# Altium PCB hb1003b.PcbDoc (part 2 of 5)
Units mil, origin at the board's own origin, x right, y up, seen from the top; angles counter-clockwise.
Board outline 2757 x 3548 mil, 2 copper layers (Top Layer, Bottom Layer); 120 components, 120 nets, 466 pads, 329 vias.
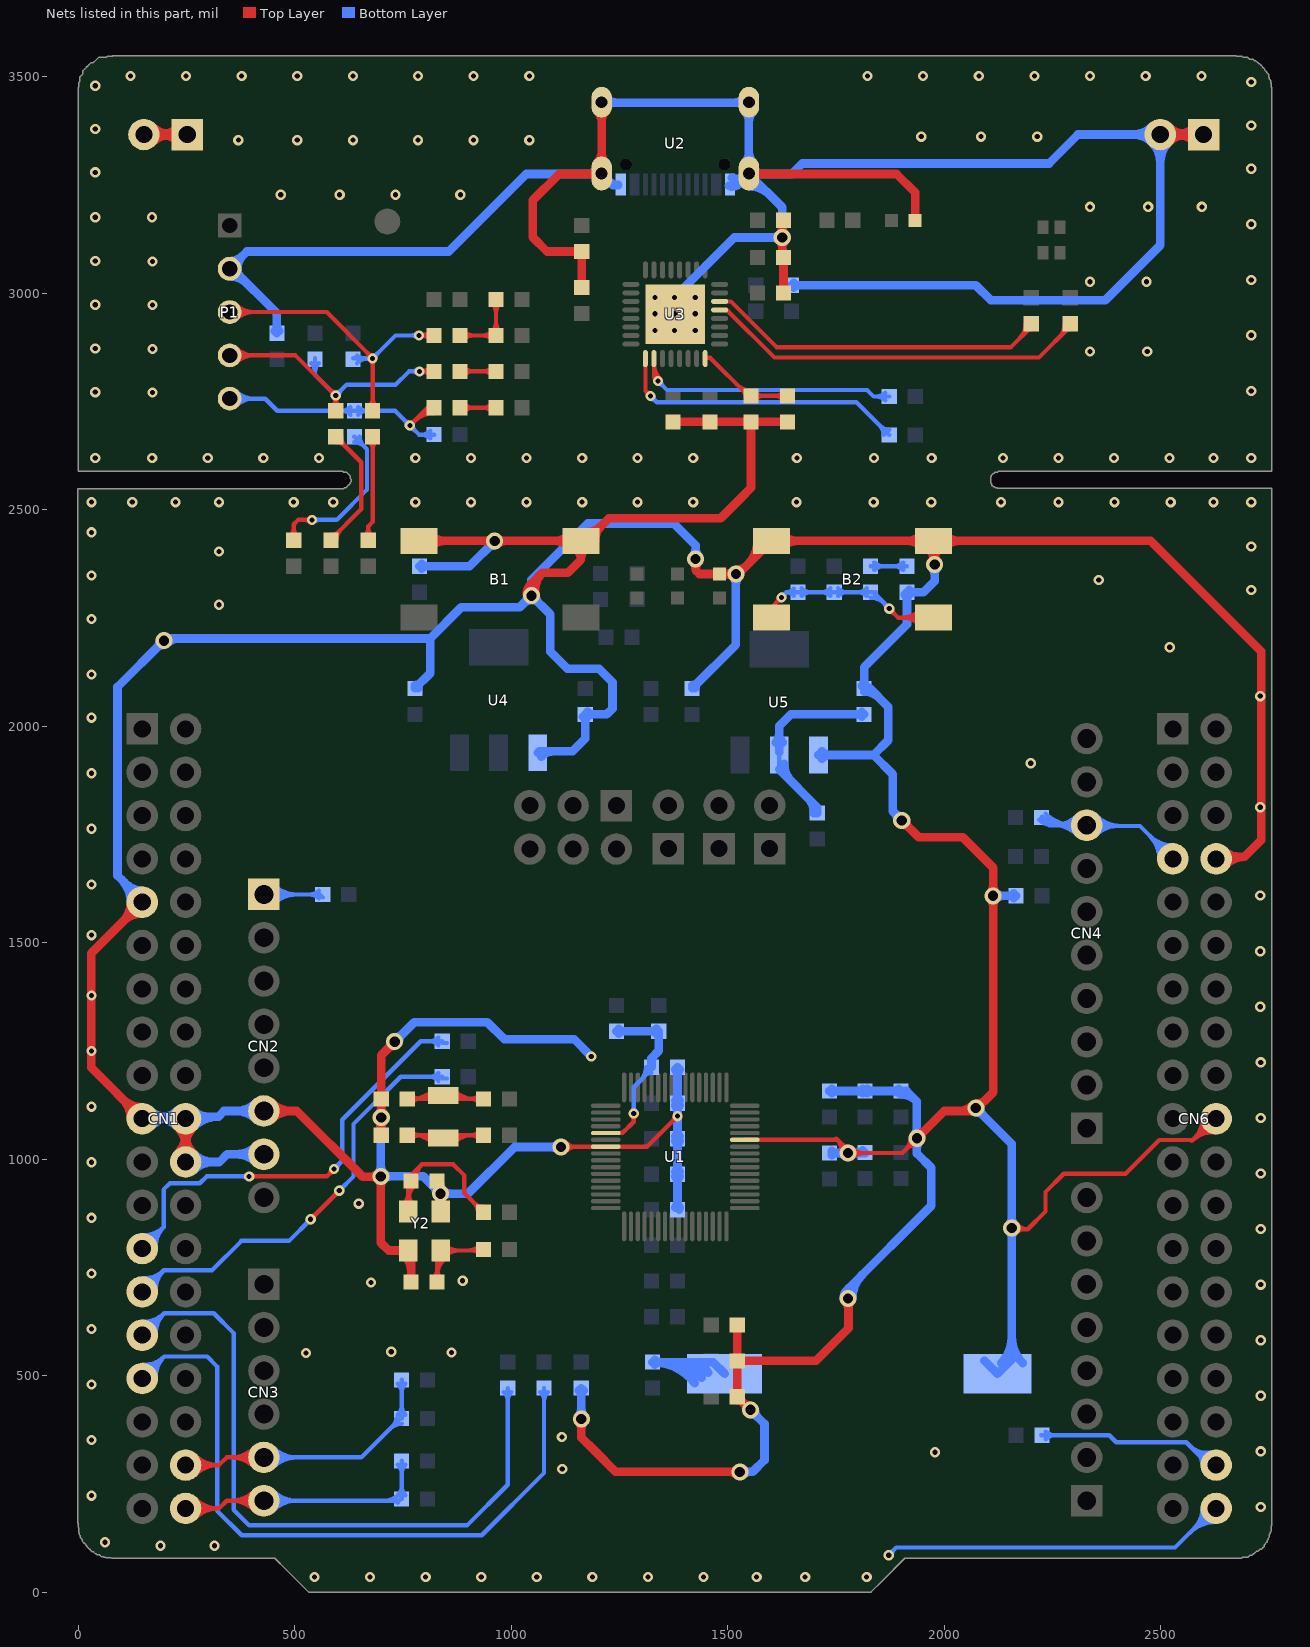
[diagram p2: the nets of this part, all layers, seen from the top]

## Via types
v1: diameter 23.62, hole 11.81, Top Layer to Bottom Layer, tented both sides, 290 vias
v2: diameter 39.37, hole 23.62, Top Layer to Bottom Layer, tented both sides, 29 vias
v3: diameter 15, hole 8, Top Layer to Bottom Layer, tented both sides, 10 vias

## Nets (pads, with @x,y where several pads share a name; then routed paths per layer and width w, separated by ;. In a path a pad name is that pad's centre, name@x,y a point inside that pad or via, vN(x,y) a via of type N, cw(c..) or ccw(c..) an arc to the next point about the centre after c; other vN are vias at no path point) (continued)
GND: B1.1 B1.2 B2.1 B2.2 BT1.2 C1.1 C2.2 C3.1 C4.2 C5.1 C6.1 C9.2 C11.2 C12.2 C13.2 C14.2 C15.2 C16.2 C17.2 C18.2 C19.2 C20.1 C21.1 C22.1 C23.1 C24.1 C25.1 C26.1 C27.1 C28.1 C29.2 C30.2 C31.1 C32.2 C34.1 C35.2 C36.1 CN1.9 CN1.19 CN1.20 CN1.22 CN2.6 CN2.7 CN6.8 CN6.20 CN6.38 D3.2 D4.2 JP2.1 JP2.2 JP3.1 JP3.2 P1.2 R5.2 R11.2 R25.2 R28.2 U1.7 U1.43 U2.1 U2.2 U2.3 U2.4 U2.A1 U2.A12 U2.B1 U2.B12 U3.33 U4.1 U5.1 Y2.2 Y2.4 | length 31589.5
  Top Layer w10: CN1.22@248,998 CN1.22@251,995 ; CN2.7@424,995 CN2.7@428,999 ; C5.1@700,1139 C5.1@709,1148 ; v2@1113.62,1028.62 U1.7@1218.57,1028.62 1313.62,1028.62 v1(1384,1099) ; v2@1125.38,1017.62 cw(c1151.95,991.05) 1151.95,1028.62 ; v2@1125.38,1038.38 ccw(c1148.95,1061.95) 1148.95,1028.62 ; B1.2@1155.58,2427.58 B1.2@1161.01,2427.58 ; v1@1377.19,1099 cw(c1360.75,1099) 1372.37,1087.37 cw(c1384,1075.75) v1@1384,1092.19 ; U1.43@1539.43,1044.37 1753.63,1044.37 v2@1778,1020 ; 1750.63,1047.37 cw(c1719.87,1016.61) v2@1763.33,1014.66 ; 1763.17,1034.83 ccw(c1778,1049.65) v2@1778,1028.68 ; 1766.68,1031.32 cw(c1750.58,1015.23) v2@1773.32,1014.21 ; v2(1778,1014) 1903,1014 v2(1937,1048) ; v2@1788.38,1003.62 cw(c1813.45,978.55) 1813.45,1014 cw(c1813.45,1049.45) v2@1788.38,1024.38 ; v2@1922.31,1048 cw(c1886.86,1048) 1911.93,1022.93 cw(c1937,997.86) v2@1937,1033.31 ; v2@2156,838 2193,838 ; v2@2166.38,830.62 cw(c2184.21,812.79) 2184.21,838 ; v2@2167.43,850.22 ccw(c2193,870.86) 2193,838 ; 2571.62,1041.62 cw(c2620.96,992.27) CN6.20@2625.81,1061.89 ; 2577.74,1047.74 ccw(c2532.26,1093.23) CN6.20@2596.58,1093.23 ; 2587.14,1057.14 cw(c2622.98,1021.29) CN6.20@2626.51,1071.86 ; 2594.81,1064.81 ccw(c2566.4,1093.23) CN6.20@2606.58,1093.23 ; CN6.20@2625.61,1095.61 2574,1044 2496.58,1044 2418.58,966 2276,966 2234,924 2234,879 2193,838
  Top Layer w20: CN1.19@121.58,1093.23 ccw(c57.81,1093.23) 102.9,1138.33 ccw(c148,1183.42) CN1.19@148,1119.65 ; CN1.9@121.58,1593.23 cw(c57.81,1593.23) 102.9,1548.13 cw(c148,1503.03) CN1.9@148,1566.81 ; CN1.19@148,1093.23 30,1211.23 30,1475.23 CN1.9@148,1593.23 ; JP3.2@152,3366 JP3.1@252,3366 ; JP3.2@170.68,3347.32 cw(c215.78,3302.22) 215.78,3366 cw(c215.78,3429.78) JP3.2@170.68,3384.68 ; CN1.22@229.32,1011.91 ccw(c184.22,1057.01) 248,1057.01 ccw(c311.78,1057.01) CN1.22@266.68,1011.91 ; CN1.20@229.32,1074.55 cw(c184.22,1029.45) 248,1029.45 cw(c311.78,1029.45) CN1.20@266.68,1074.55 ; JP3.1@233.32,3347.32 ccw(c188.22,3302.22) 188.22,3366 ccw(c188.22,3429.78) JP3.1@233.32,3384.68 ; CN1.22@248,998 CN1.20@248,1098 ; CN2.6@429,1111 505,1111 657,959 696,959 v2@700,963 ; CN2.6@447.68,1092.32 cw(c492.78,1047.22) 492.78,1111 cw(c492.78,1174.78) CN2.6@447.68,1129.68 ; 673.2,959 ccw(c673.2,985.8) v2@692.15,966.85 ; 678.03,959 cw(c678.03,939.03) 692.15,953.15 cw(c675.62,936.62) 699,936.62 cw(c722.38,936.62) v2@705.85,953.15 ; v2@693.15,1089.15 cw(c676.62,1072.62) 700,1072.62 cw(c723.38,1072.62) v2@706.85,1089.15 ; v2@693.15,1102.85 ccw(c676.62,1119.38) 700,1119.38 ccw(c723.38,1119.38) v2@706.85,1102.85 ; C6.1@694.7,1060.3 ccw(c681.89,1073.11) 700,1073.11 ccw(c718.11,1073.11) C6.1@705.3,1060.3 ; C5.1@694.7,1133.7 cw(c681.89,1120.89) 700,1120.89 cw(c718.11,1120.89) C5.1@705.3,1133.7 ; C5.1@694.7,1144.3 ccw(c681.89,1157.11) 700,1157.11 ccw(c718.11,1157.11) C5.1@705.3,1144.3 ; 699,850 699,893 ; v2(699,960) 699,893 ; C6.1@700,1055 C5.1@700,1139 700,1240 v2(731,1271) ; v2@721.32,1271 cw(c697.93,1271) 714.47,1254.47 cw(c731,1237.93) v2@731,1261.32 ; Y2.2@754.36,776.55 cw(c719.01,741.2) 769,741.2 ; Y2.2@754.36,780.48 ccw(c734.46,760.59) 734.46,788.72 ccw(c734.46,816.86) Y2.2@754.36,796.96 ; C12.2@763.7,721.3 ccw(c750.89,734.11) 769,734.11 ccw(c787.11,734.11) C12.2@774.3,721.3 ; C12.2@769,716 769,782.32 Y2.2@762.6,788.72 717.28,788.72 699,807 699,893 ; B1.1@786.99,2427.58 B1.2@1155.58,2427.58 ; B1.1@813.68,2413.5 cw(c847.68,2379.49) 847.68,2427.58 cw(c847.68,2475.68) B1.1@813.68,2441.67 ; C11.2@823.7,943.7 cw(c790.61,910.61) v2@837.4,910.61 ; C11.2@829,949 C11.2@837.4,940.6 ; Y2.4@829.16,891.45 ccw(c809.27,911.35) 837.4,911.35 ccw(c865.54,911.35) Y2.4@845.64,891.45 ; v2@830.15,913.15 cw(c812.65,895.65) Y2.4@837.4,895.65 ; v2@831.06,927.65 ccw(c821.01,940.6) C11.2@837.4,940.6 ; Y2.4@837.4,879.28 C11.2@837.4,940.6 ; Y2.4@837.4,897.59 cw(c859.41,897.59) v2@843.85,913.15 ; v2@843.41,927.26 cw(c855.21,940.6) C11.2@837.4,940.6 ; 937.21,2427.58 cw(c937.21,2402.21) v2@955.15,2420.15 ; 940.03,2427.58 ccw(c940.03,2448.97) v2@955.15,2433.85 ; v2@968.85,2420.15 cw(c986.79,2402.21) 986.79,2427.58 ; v2@968.85,2433.85 ccw(c983.97,2448.97) 983.97,2427.58 ; v2@1036.88,2298.99 cw(c1067.92,2305.16) 1045.54,2327.54 ; v2@1040.15,2307.85 ccw(c1023.62,2324.38) 1047,2324.38 ccw(c1070.38,2324.38) v2@1053.85,2307.85 ; v2(1047,2301) 1047,2329 1072,2354 ; 1050,3156 1050,3179 ; v2@1056.5,2302.89 cw(c1112.05,2313.95) 1072,2354 ; B1.2@1134.32,2413.5 ccw(c1100.32,2379.49) 1100.32,2427.58 ccw(c1100.32,2475.68) B1.2@1134.32,2441.67 ; B1.2@1147.97,2412.52 cw(c1123.32,2384.01) 1161.01,2384.01 ; v2@1155.15,393.15 cw(c1138.62,376.62) 1162,376.62 cw(c1185.38,376.62) v2@1168.85,393.15 ; C29.2@1157.7,3018.3 ccw(c1144.89,3031.11) 1163,3031.11 ccw(c1181.11,3031.11) C29.2@1168.3,3018.3 ; C31.1@1157.7,3101.3 cw(c1144.89,3114.11) 1144.89,3096 cw(c1144.89,3077.89) 1157.7,3090.7 cw(c1144.89,3077.89) 1163,3077.89 cw(c1181.11,3077.89) C31.1@1168.3,3090.7 ; v2(1162,400) 1162,357 1194,325 1241,278 v2@1528,278 ; C29.2@1163,3006 C31.1@1163,3096 1083,3096 1050,3129 1050,3179 ; B1.2@1173.61,2447.5 ccw(c1173.61,2495.54) 1207.57,2461.57 ; 1173.7,3275 ccw(c1173.7,3311.3) U2.1@1199.37,3285.63 ; B1.2@1174.04,2412.52 ccw(c1198.7,2384.01) 1161.01,2384.01 ; 1178.53,3275 cw(c1178.53,3245.53) U2.1@1199.37,3266.37 ; B1.2@1193.53,2427.58 cw(c1241.68,2427.58) 1207.63,2461.63 ; U2.1@1199.37,3301.38 ccw(c1176.49,3324.26) 1208.84,3324.26 ; U2.3@1199.37,3419.12 cw(c1176.49,3396.25) 1208.84,3396.25 ; 1208.84,3325.01 ccw(c1242.26,3325.01) U2.1@1218.63,3301.38 ; 1208.84,3395.49 cw(c1242.26,3395.49) U2.3@1218.63,3419.12 ; U2.3@1208.84,3439.57 1208.84,3275 1111,3275 1050,3214 1050,3179 ; C21.1@1369,2703 1459,2703 C28.1@1633,2703 ; C21.1@1379.3,2696.7 cw(c1394.52,2681.48) 1394.52,2703 ; v2(1426,2386) 1426,2360 1435,2351 D3.2@1481,2351 v2(1519,2351) 1524.41,2351 B2.1@1600.99,2427.58 B2.2@1975.01,2427.58 2476.42,2427.58 2732,2172 2732,1736.66 2693.34,1698 ; 1438.48,2703 cw(c1438.48,2681.48) C20.1@1453.7,2696.7 ; C20.1@1464.3,2696.7 cw(c1479.52,2681.48) 1479.52,2703 ; 1502.2,278 cw(c1502.2,251.2) v2@1521.15,270.15 ; 1507.03,278 ccw(c1507.03,297.97) v2@1521.15,283.85 ; v2@1512.15,2344.15 ccw(c1495.62,2327.62) 1495.62,2351 ccw(c1495.62,2374.38) v2@1512.15,2357.85 ; C13.2@1516.7,456.3 ccw(c1503.89,469.11) 1522,469.11 ccw(c1540.11,469.11) C13.2@1527.3,456.3 ; C14.2@1516.7,528.7 cw(c1503.89,515.89) 1522,515.89 cw(c1540.11,515.89) 1527.3,528.7 cw(c1540.11,515.89) 1540.11,534 cw(c1540.11,552.11) 1527.3,539.3 cw(c1540.11,552.11) 1522,552.11 cw(c1503.89,552.11) C14.2@1516.7,539.3 ; C15.2@1516.7,611.7 cw(c1503.89,598.89) 1522,598.89 cw(c1540.11,598.89) C15.2@1527.3,611.7 ; v2@1519,2360.69 ccw(c1519,2397.13) 1544.77,2371.36 ; C13.2@1522,443.5 cw(c1522,425.39) 1534.8,438.2 cw(c1547.61,451) C13.2@1529.5,451 ; C15.2@1522,617 C14.2@1522,534 ; 1533.48,2703 cw(c1533.48,2681.48) 1548.7,2696.7 cw(c1535.89,2683.89) 1554,2683.89 cw(c1572.11,2683.89) 1559.3,2696.7 cw(c1574.52,2681.48) 1574.52,2703 ; C13.2@1534.76,438.24 ccw(c1553,456.48) v2@1553,430.68 ; C13.2@1537.17,435.82 cw(c1522.35,421) v2@1543.32,421 ; 1540,2536 1518.5,2514.5 ; 1545.48,2372.07 ccw(c1489.96,2427.58) B2.1@1568.47,2427.58 ; U2.2@1549,3275 1890,3275 1933,3232 D4.2@1933,3168 ; v2@1550,423 C13.2@1522,451 C14.2@1522,534 ; C22.1@1554,2702 1554,2550 1518.5,2514.5 ; U2.2@1558.79,3266.37 cw(c1579.63,3245.53) 1579.63,3275 ; U2.2@1558.79,3285.63 ccw(c1584.46,3311.3) 1584.46,3275 ; 1617.48,2703 cw(c1617.48,2681.48) C28.1@1632.7,2696.7 ; v2@1619.15,3121.15 cw(c1602.62,3104.62) 1626,3104.62 cw(c1649.38,3104.62) v2@1632.85,3121.15 ; v2@1619.15,3134.85 ccw(c1602.62,3151.38) 1626,3151.38 ccw(c1649.38,3151.38) v2@1632.85,3134.85 ; C35.2@1623.7,3005.3 ccw(c1610.89,3018.11) 1629,3018.11 ccw(c1647.11,3018.11) C35.2@1634.3,3005.3 ; C32.2@1623.7,3076.7 cw(c1610.89,3063.89) 1629,3063.89 cw(c1647.11,3063.89) C32.2@1634.3,3076.7 ; C32.2@1626,3085 C34.1@1626,3168 ; 1626,3107.35 ccw(c1654.35,3107.35) C32.2@1634.3,3087.3 ; v2@1626,3142.65 cw(c1654.35,3142.65) C34.1@1634.3,3162.7 ; B2.1@1627.68,2413.5 cw(c1661.68,2379.49) 1661.68,2427.58 cw(c1661.68,2475.68) B2.1@1627.68,2441.67 ; C35.2@1629,3000 C32.2@1629,3082 ; v2@1771.15,671.15 cw(c1752.2,652.2) 1779,652.2 ; 1779,657.03 cw(c1798.97,657.03) v2@1784.85,671.15 ; v2@1779,678 1779,609 1704,534 C14.2@1522,534 ; v2@1902,1772.32 cw(c1902,1748.93) 1918.53,1765.47 cw(c1935.07,1782) v2@1911.68,1782 ; v2(1902,1782) 1941,1743 2043,1743 2113,1673 v2(2113,1608) ; v2(1937,1048) 2000,1111 2070,1111 2113,1154 v2(2113,1608) ; v2@1937,1057.68 ccw(c1937,1081.07) 1953.53,1064.53 ccw(c1970.07,1048) v2@1946.68,1048 ; B2.2@1948.32,2413.5 ccw(c1914.32,2379.49) 1914.32,2427.58 ccw(c1914.32,2475.68) B2.2@1948.32,2441.67 ; B2.2@1961.04,2413.38 cw(c1921.26,2372.92) v2@1978,2372.92 ; v2@1971.15,2379.85 ccw(c1954.62,2396.38) 1978,2396.38 ccw(c2001.38,2396.38) v2@1984.85,2379.85 ; v2(1978,2373) B2.2@1978,2424.59 ; v2@1978,2386.71 cw(c2015.88,2386.71) B2.2@1989.09,2413.5 ; B2.2@2001.69,2413.5 cw(c2035.7,2379.49) 2035.7,2427.58 cw(c2035.7,2475.68) B2.2@2001.69,2441.67 ; 2032.72,1111 ccw(c2032.72,1158.28) v2@2066.15,1124.85 ; v2@2073,1127.68 ccw(c2073,1160.72) 2096.36,1137.36 ; v2@2106.15,1601.15 cw(c2089.62,1584.62) 2113,1584.62 cw(c2136.38,1584.62) v2@2119.85,1601.15 ; v2@2106.15,1614.85 ccw(c2089.62,1631.38) 2113,1631.38 ccw(c2136.38,1631.38) v2@2119.85,1614.85 ; v2@2115,1606 v2(2113,1608) ; JP2.2@2499,3366 JP2.1@2599,3366 ; JP2.2@2517.68,3347.32 cw(c2562.78,3302.22) 2562.78,3366 cw(c2562.78,3429.78) JP2.2@2517.68,3384.68 ; JP2.1@2580.32,3347.32 ccw(c2535.22,3302.22) 2535.22,3366 ccw(c2535.22,3429.78) JP2.1@2580.32,3384.68 ; CN6.8@2628,1698 2693.34,1698 ; CN6.8@2646.68,1711.91 ccw(c2680.26,1745.48) 2680.26,1698 ; CN6.8@2648.54,1676.62 cw(c2693.33,1640.4) 2693.33,1698 ; 1072,2354 1131,2354 1161.01,2384.01 ; 1161.01,2384.01 B1.2@1161.01,2427.58 1173.58,2427.58 1226,2480 1484,2480 1518.5,2514.5 ; 1426,2362.62 cw(c1449.38,2362.62) 1432.85,2379.15 ccw(c1449.38,2362.62) 1426,2362.62 ; 1426,2362.62 ccw(c1402.62,2362.62) 1419.15,2379.15 cw(c1402.62,2362.62) 1426,2362.62
  Bottom Layer w10: v1(1185,1237) v1@1185.5,1236.5 ; v1@1872,86 1880,94 1889,103 2533,103 CN6.38@2628,198 ; v1@1872,91.81 ccw(c1872,105.84) 1881.92,95.92 ; v1@1878.81,85 cw(c1897.67,85) 1884.33,98.33 ; 2566.22,136.22 cw(c2628,74.44) CN6.38@2628,161.81 ; 2577.74,147.74 ccw(c2532.26,193.23) CN6.38@2596.58,193.23 ; 2583.29,153.29 cw(c2628,108.58) CN6.38@2628,171.81 ; 2594.81,164.81 ccw(c2566.4,193.23) CN6.38@2606.58,193.23
  Bottom Layer w20: 99.53,1646.47 cw(c46.29,1593.23) CN1.9@121.58,1593.23 ; 111.05,1634.95 ccw(c148,1671.9) CN1.9@148,1619.65 ; CN1.19@148,1098 248,1098 324,1098 337,1111 CN2.6@429,1111 ; CN1.9@148,1598 91,1655 91,2090 v2(198,2197) 203,2202 813,2202 ; CN1.19@166.68,1074.55 cw(c223.3,1017.93) CN1.20@223.3,1098 ; CN1.19@166.68,1111.91 ccw(c200.26,1145.48) 200.26,1098 ; CN1.19@172.7,1098 cw(c172.7,1017.93) CN1.20@229.32,1074.55 ; v2@188.32,2197 cw(c164.93,2197) 181.47,2180.47 cw(c198,2163.93) v2@198,2187.31 ; 195.74,1098 ccw(c195.74,1145.48) CN1.20@229.32,1111.91 ; v2@204.85,2190.15 cw(c233.45,2161.55) 233.45,2202 ; CN1.22@248,993.23 326.23,993.23 344,1011 CN2.7@429,1011 ; CN1.22@266.68,974.55 cw(c311.78,929.45) 311.78,993.23 cw(c311.78,1057.01) CN1.22@266.68,1011.91 ; CN1.20@266.68,1074.55 cw(c323.3,1017.93) 323.3,1098 ; CN1.20@266.68,1111.91 ccw(c300.26,1145.48) 300.26,1098 ; P1.2@350,3038.5 cw(c350,2981.77) 390.12,3021.88 ; P1.2@350,3073.5 ccw(c350,3115.75) 379.87,3085.87 ccw(c409.75,3056) 367.5,3056 ccw(c395.26,3056) 375.63,3036.37 ; CN2.7@410.32,992.32 ccw(c365.22,947.22) 365.22,1011 ccw(c365.22,1074.78) CN2.7@410.32,1029.68 ; CN2.6@410.32,1092.32 ccw(c365.22,1047.22) 365.22,1111 ccw(c365.22,1174.78) CN2.6@410.32,1129.68 ; R28.2@453.7,2912.3 ccw(c440.89,2925.11) 459,2925.11 ccw(c477.11,2925.11) R28.2@464.3,2912.3 ; R28.2@459,2907 459,2953 356,3056 P1.2@350,3056 390,3096 546,3096 ; 572,3096 546,3096 ; 680,3096 632,3096 ; v2@692.15,966.85 ccw(c675.62,983.38) 699,983.38 ccw(c722.38,983.38) 705.85,966.85 ccw(c722.38,983.38) 722.38,960 ccw(c722.38,936.62) v2@705.85,953.15 ; v2@693.15,1089.15 cw(c679.03,1075.03) 699,1075.03 ; 699,1070.2 cw(c725.8,1070.2) v2@706.85,1089.15 ; v2@699,1089 v2(699,960) 797,960 v2(837,920) 900,920 1008,1028 v2(1115,1028) ; v2(731,1271) 776,1316 945,1316 984,1277 1145,1277 v1(1185,1237) ; v2@731,1280.68 ccw(c731,1304.07) 747.53,1287.53 ccw(c764.07,1271) v2@740.68,1271 ; C23.1@778,2087 813,2122 813,2202 ; C23.1@778,2094.5 ccw(c778,2112.61) 790.8,2099.8 ccw(c803.61,2087) C23.1@785.5,2087 ; C2.2@788,2369 904,2369 v2(962,2427) ; C2.2@793.3,2363.7 cw(c806.11,2350.89) 806.11,2369 cw(c806.11,2387.11) C2.2@793.3,2374.3 ; v2@827.32,920 ccw(c803.93,920) 820.47,936.53 ccw(c837,953.07) v2@837,929.68 ; v2@843.85,913.15 cw(c860.38,896.62) 860.38,920 cw(c860.38,943.38) v2@843.85,926.85 ; v2@952.32,2427 cw(c928.93,2427) 945.47,2410.47 cw(c962,2393.93) v2@962,2417.31 ; v2@1037.32,2301 cw(c1013.93,2301) 1030.47,2284.47 cw(c1047,2267.93) 1047,2291.31 cw(c1047,2267.93) 1063.53,2284.47 cw(c1080.07,2301) v2@1056.68,2301 ; v2@1040.15,2307.85 ccw(c1023.62,2324.38) 1047,2324.38 ccw(c1070.38,2324.38) v2@1053.85,2307.85 ; U4.1@1061.55,1937.95 1065.1,1941.5 1141.5,1941.5 1171,1971 C25.1@1171,2027 1221,2027 1234,2040 1234,2101 1203,2132 1130,2132 1090,2172 1090,2258 v2(1047,2301) ; U4.1@1069.79,1929.71 cw(c1098.25,1901.26) 1098.25,1941.5 ; v2@1108.15,1021.15 ccw(c1091.62,1004.62) 1091.62,1028 ccw(c1091.62,1051.38) v2@1108.15,1034.85 ; v2@1155.15,406.85 ccw(c1138.62,423.38) 1162,423.38 ccw(c1185.38,423.38) v2@1168.85,406.85 ; R11.2@1156.7,465.7 cw(c1143.89,452.89) 1162,452.89 cw(c1180.11,452.89) R11.2@1167.3,465.7 ; v2(1162,400) R11.2@1162,471 ; C25.1@1165.7,2021.7 cw(c1152.89,2008.89) 1171,2008.89 cw(c1189.11,2008.89) 1176.3,2021.7 cw(c1189.11,2008.89) 1189.11,2027 cw(c1189.11,2045.11) C25.1@1176.3,2032.3 ; 1173.7,3275 ccw(c1173.7,3311.3) U2.1@1199.37,3285.63 ; 1178.53,3275 cw(c1178.53,3245.53) U2.1@1199.37,3266.37 ; U2.3@1208.84,3439.57 1549,3439.57 U2.2@1549,3275 ; U2.3@1218.63,3430.93 cw(c1239.47,3410.09) 1239.47,3439.57 ; U2.3@1218.63,3450.2 ccw(c1244.3,3475.87) 1244.3,3439.57 ; U2.1@1221.4,3265.9 ccw(c1247.03,3277.57) 1247.03,3249.4 1234.44,3249.4 1208.84,3275 1035,3275 856,3096 632,3096 ; v1(1377,2990) 1515,3128 v2(1626,3128) ; C1.1@1378.7,888.3 ccw(c1365.89,901.11) 1384,901.11 ccw(c1402.1,901.1) C1.1@1389.3,888.3 ; C3.1@1378.7,959.7 cw(c1365.89,946.89) 1384,946.89 cw(c1402.1,946.89) C3.1@1389.3,959.7 ; C3.1@1378.7,970.3 ccw(c1365.89,983.11) 1384,983.11 ccw(c1402.11,983.11) C3.1@1389.3,970.3 ; C9.2@1378.7,1041.7 cw(c1365.89,1028.89) 1384,1028.89 cw(c1402.11,1028.89) C9.2@1389.3,1041.7 ; C9.2@1378.7,1052.3 ccw(c1365.89,1065.11) 1384,1065.11 ccw(c1402.11,1065.11) C9.2@1389.3,1052.3 ; C4.2@1378.7,1123.7 cw(c1365.89,1110.89) 1384,1110.89 cw(c1402.11,1110.89) C4.2@1389.3,1123.7 ; C4.2@1378.7,1134.3 ccw(c1365.89,1147.11) 1384,1147.11 ccw(c1402.11,1147.11) C4.2@1389.3,1134.3 ; C24.1@1378.7,1206.7 cw(c1365.89,1193.89) 1384,1193.89 cw(c1402.11,1193.89) C24.1@1389.3,1206.7 ; C3.1@1384,964 1384,887.5 C1.1@1388.5,883 ; C3.1@1384,965 C9.2@1384,1047 C4.2@1384,1129 C24.1@1384,1212 ; C26.1@1418,2087 1519,2188 v2(1519,2351) ; C26.1@1418,2094.5 ccw(c1418,2112.61) 1430.8,2099.8 ccw(c1443.61,2087) C26.1@1425.5,2087 ; v2@1419.15,2392.85 ccw(c1402.62,2409.38) 1426,2409.38 ccw(c1449.38,2409.38) v2@1432.85,2392.85 ; v2(1426,2386) 1426,2417 1375.31,2467.69 1176.69,2467.69 1047,2338 v2(1047,2301) ; U2.B1@1502.75,3247.44 ccw(c1510.57,3268.98) 1526.78,3252.78 ; U2.A12@1509.57,3266.24 ccw(c1522.4,3301.6) U2.2@1549,3275 ; v2@1512.15,2344.15 cw(c1495.62,2327.62) 1519,2327.62 cw(c1542.38,2327.62) v2@1525.85,2344.15 ; 1513.86,3439.57 ccw(c1513.86,3475.87) U2.4@1539.52,3450.2 ; 1518.68,3439.57 cw(c1518.68,3410.09) U2.4@1539.52,3430.93 ; v2@1529,278 1558,278 1585,305 1585,388 v2@1552.5,420.5 ; v2@1534.85,270.15 cw(c1553.8,251.2) 1553.8,278 ; v2@1534.85,283.85 ccw(c1548.97,297.97) 1548.97,278 ; U2.2@1536.8,3265.99 cw(c1510.81,3278.05) 1510.81,3249.4 1523.4,3249.4 U2.2@1549,3275 ; U2.2@1539.52,3301.38 ccw(c1516.65,3324.26) 1549,3324.26 ; U2.4@1539.52,3419.12 cw(c1516.65,3396.25) 1549,3396.25 ; 1549,3325.01 ccw(c1582.42,3325.01) U2.2@1558.79,3301.38 ; 1549,3395.49 cw(c1582.42,3395.49) U2.4@1558.79,3419.12 ; U2.2@1549.16,3246.63 cw(c1549.16,3178.52) 1597.32,3226.68 ; U2.2@1549.16,3275 1648,3275 1672,3299 2242,3299 2309,3366 JP2.2@2499,3366 2499,3110 2372,2983 2108,2983 2073,3018 C30.2@1647,3018 ; v2@1553,411.32 cw(c1553,390.35) 1567.83,405.17 ; U2.2@1558.79,3266.37 cw(c1579.63,3245.53) 1579.63,3275 ; U2.2@1558.79,3285.63 ccw(c1584.46,3311.3) 1584.46,3275 ; v2@1562.68,421 ccw(c1588.48,421) 1570.24,402.76 ; v2@1619.15,3121.15 ccw(c1602.62,3104.62) 1602.62,3128 ccw(c1602.62,3151.38) v2@1619.15,3134.85 ; C30.2@1652.3,3012.7 cw(c1665.11,2999.89) 1665.11,3018 cw(c1665.11,3036.11) C30.2@1652.3,3023.3 ; U5.1@1709.55,1932.95 1836.95,1932.95 ; U5.1@1717.79,1924.71 cw(c1737.69,1904.82) 1737.69,1932.95 cw(c1737.69,1961.09) U5.1@1717.79,1941.19 ; C17.2@1735,1157 C19.2@1817,1157 C36.1@1900,1157 1913,1157 1937,1133 v2(1937,1048) 1937,1013 1970,980 1970,892 1779,701 ; C18.2@1740.3,1008.7 cw(c1753.11,995.89) 1753.11,1014 cw(c1753.1,1032.1) C18.2@1740.3,1019.3 ; C17.2@1740.3,1151.7 cw(c1753.11,1138.89) 1753.11,1157 cw(c1753.11,1175.11) C17.2@1740.3,1162.3 ; C18.2@1741,1014 v2(1778,1014) C16.2@1817,1014 ; v2@1767.69,678 cw(c1795.9,678) 1775.95,697.95 ; v2@1771.15,1007.15 ccw(c1754.62,990.62) 1754.62,1014 ccw(c1754.62,1037.38) v2@1771.15,1020.85 ; v2@1771.75,685.4 ccw(c1758.59,701) 1779,701 ; v2@1779,686 1779,701 ; 1779,698.97 ccw(c1798.97,698.97) v2@1784.85,684.85 ; v2@1784.85,1007.15 cw(c1801.38,990.62) 1801.38,1014 cw(c1801.38,1037.38) v2@1784.85,1020.85 ; v2@1787.68,678 cw(c1864.18,678) 1810.09,732.09 ; v2@1796.48,1014 ccw(c1796.48,1035.52) C16.2@1811.7,1020.3 ; C27.1@1809.7,2092.3 ccw(c1796.89,2105.11) 1815,2105.11 ccw(c1833.11,2105.11) C27.1@1820.3,2092.3 ; C19.2@1811.7,1151.7 ccw(c1798.89,1138.89) 1798.89,1157 ccw(c1798.89,1175.11) C19.2@1811.7,1162.3 ; C27.1@1815,2079.5 cw(c1815,2030.01) 1850,2065.01 ; C27.1@1815,2087 1815,2136 1914,2235 R5.2@1914,2309 1952,2309 1978,2335 v2(1978,2373) ; C19.2@1822.3,1151.7 cw(c1835.11,1138.89) 1835.11,1157 cw(c1835.11,1175.11) C19.2@1822.3,1162.3 ; C27.1@1828,2087 1871,2044 1871,1967 1836.95,1932.95 ; v2@1892.32,1782 ccw(c1868.93,1782) 1885.47,1798.53 ccw(c1902,1815.07) v2@1902,1791.68 ; C36.1@1894.7,1151.7 ccw(c1881.89,1138.89) 1881.89,1157 ccw(c1881.89,1175.11) C36.1@1894.7,1162.3 ; C36.1@1900,1149.5 cw(c1900,1100.01) 1935,1135 ; v2(1902,1782) 1880.95,1803.05 1880.95,1888.95 1836.95,1932.95 ; R5.2@1908.7,2303.7 cw(c1895.89,2290.89) 1914,2290.89 cw(c1932.11,2290.89) 1919.3,2303.7 cw(c1932.11,2290.89) 1932.11,2309 cw(c1932.11,2327.11) R5.2@1919.3,2314.3 ; v2@1930.15,1041.15 cw(c1913.62,1024.62) 1937,1024.62 cw(c1960.38,1024.62) v2@1943.85,1041.15 ; v2@1930.15,1054.85 ccw(c1913.62,1071.38) 1937,1071.38 ccw(c1960.38,1071.38) v2@1943.85,1054.85 ; v2@1971.15,2366.15 cw(c1954.62,2349.62) 1978,2349.62 cw(c2001.38,2349.62) v2@1984.85,2366.15 ; v2@2073,1108.32 cw(c2073,1084.93) 2089.53,1101.47 cw(c2106.07,1118) v2@2082.68,1118 ; v2(2073,1118) 2156,1035 v2@2156,851 ; BT1.2@2093,533.92 BT1.2@2122.92,504 2156,537.08 v2(2156,841) ; v2(2113,1608) R25.2@2166,1608 R25.2@2164,1606 ; v2@2119.85,1601.15 cw(c2136.38,1584.62) 2136.38,1608 cw(c2136.38,1631.38) v2@2119.85,1614.85 ; BT1.2@2131.44,528.94 ccw(c2072.15,588.23) 2156,588.23 ; v2@2149.15,834.15 cw(c2132.62,817.62) 2156,817.62 cw(c2179.38,817.62) v2@2162.85,834.15 ; v2@2149.15,847.85 ccw(c2132.62,864.38) 2156,864.38 ccw(c2179.38,864.38) v2@2162.85,847.85 ; 2156,590.09 ccw(c2242.48,590.09) BT1.2@2181.33,528.94 ; R25.2@2160.7,1602.7 ccw(c2147.89,1589.89) 2147.89,1608 ccw(c2147.89,1626.11) R25.2@2160.7,1613.3 ; JP2.2@2480.32,3384.68 cw(c2435.22,3429.78) 2435.22,3366 cw(c2435.22,3302.22) 2480.32,3347.32 cw(c2435.22,3302.22) 2499,3302.22 cw(c2562.78,3302.22) JP2.2@2517.68,3347.32 ; 546,3096 632,3096 ; 813,2202 885,2274 1020,2274 v2(1047,2301) ; U2.2@1549,3275 1626,3198 ; v2@1619.15,3134.85 ccw(c1602.62,3151.38) 1626,3151.38 ; v2@1619.15,3134.85 ccw(c1602.62,3151.38) 1626,3151.38 ; v2(1626,3128) 1626,3198 ; v2(1626,3128) 1626,3198 ; 1626,3151.38 ccw(c1649.38,3151.38) 1632.85,3134.85 cw(c1649.38,3151.38) 1626,3151.38
  other v1: 545.82,34.66 674.16,34.66 802.49,34.66 930.83,34.66 1059.17,34.66 1187.5,34.66 1315.84,34.66 1444.17,34.66 1567,34.66 1679,34.66 1821,34.66 1872,85 190.34,107 314.67,107 62,115 2731,196.64 31,222.64 1118,284 1979,323 2731,324.97 31,350.97 1117,358 2731,453.31 31,479.31 526,552 862,553 723,555 2731,581.64 31,607.64 2731,709.98 676,715 888,719 31,735.98 2731,838.32 31,864.32 648,897 2731,966.65 31,992.65 2731,1094.99 31,1120.99 2731,1223.32 31,1249.32 2730,1351.66 31,1377.66 2730,1479.99 31,1516.99 2730,1608.33 31,1634.33 31,1762.66 2730,1812.32 31,1891 2200,1914 31,2019.34 2730,2068.99 31,2119 2521,2182 31,2247.34 325,2280 2709,2314.34 2357,2337 31,2347.34 325,2403 2709,2414.34 31,2447.34 31,2517 125,2517 225,2517 325,2517 497.65,2517 589,2517 778.67,2517 907.01,2517 1035.67,2517 1164.01,2517 1292.01,2517 1420.34,2517 1658.77,2517 1837.18,2517 1970.04,2517 2131,2517 2263.91,2517 2393.49,2517 2523,2517 2622,2517 2709,2517 39.57,2619 170.99,2619 299.33,2619 427.66,2619 556,2619 778.67,2619 907.01,2619 1035.67,2619 1164.01,2619 1292.01,2619 1420.34,2619 1659.77,2619 1838.18,2619 1971.04,2619 2135.57,2619 2263.91,2619 2392.25,2619 2520.58,2619 2622,2619 2709,2619 171.57,2770 39.57,2771 2709,2773.99 2337,2865 2468.99,2865 171.57,2871 39.57,2872 2709,2902.33 1332,2913 1377,2913 1425,2913 1332,2952 1377,2952 1425,2952 171.57,2972 39.57,2973 1332,2990 1425,2990 2337,3026 2466.99,3026 2709,3030.33 171.57,3073 39.57,3074 2709,3158.66 39.57,3175 170.57,3175 2337,3199 2471,3199 2595,3199 468,3227 603.99,3227 733,3227 882.66,3227 39.57,3278.68 2709,3287 370,3353 505.99,3353 635,3353 784.66,3353 912.99,3353 1042,3353 1947,3361 2085,3361 2215,3361 39.57,3378.68 2709,3387 39.57,3478.68 2709,3487 120.66,3501 248.99,3501 377.66,3501 505.99,3501 635,3501 784.66,3501 912.99,3501 1042,3501 1822.99,3501 1951.33,3501 2079.99,3501 2208.33,3501 2337,3501 2465.33,3501 2594,3501
  other v2: 1528,277 1553,421 1778,678 700,1096
HED_LINK_LEDG: R33.1 U3.5 | length 940.2
  Top Layer w10: U3.5@1479.39,2960.84 1498.09,2960.84 1607.94,2851 1837,2851 2219,2851 R33.1@2291,2923 ; U3.5@1495.54,2960.33 cw(c1495.54,2952.92) 1500.78,2958.16 ; 2265.42,2897.42 ccw(c2233.84,2929) R33.1@2278.5,2929 ; R33.1@2279.9,2911.9 cw(c2291,2900.81) R33.1@2291,2916.5
HED_LINK_LEDR: R32.1 U3.6 | length 851.6
  Top Layer w10: U3.6@1479.39,2980.53 1507.38,2980.53 1612.91,2875 2154,2875 R32.1@2202,2923 ; 2174.71,2895.71 ccw(c2141.42,2929) R32.1@2188.5,2929 ; R32.1@2191.61,2912.61 cw(c2201,2903.22) R32.1@2201,2916.5 ; R32.1@2191.78,2912.78 ccw(c2175.57,2929) R32.1@2198.5,2929
HED_LINK_RESET: R38.1 R50.2 | length 177.8
  Top Layer w10: R38.1@882,2735 R50.2@965,2735 ; R38.1@890.84,2726.16 cw(c912.18,2704.82) 912.18,2735 cw(c912.18,2765.18) R38.1@890.84,2743.84 ; R50.2@956.16,2726.16 ccw(c934.82,2704.82) 934.82,2735 ccw(c934.82,2765.18) R50.2@956.16,2743.84
HED_LINK_SWCLK: R41.1 R51.2 | length 177.8
  Top Layer w10: R41.1@882,2819 R51.2@965,2819 ; R41.1@890.84,2810.16 cw(c912.18,2788.82) 912.18,2819 cw(c912.18,2849.18) R41.1@890.84,2827.84 ; R51.2@956.16,2810.16 ccw(c934.82,2788.82) 934.82,2819 ccw(c934.82,2849.18) R51.2@956.16,2827.84
HED_LINK_SWDIO: R37.1 R42.2 R43.2 | length 355.6
  Top Layer w10: R37.1@882,2902 R42.2@965,2902 R43.2@965,2985 ; R37.1@890.84,2893.16 cw(c912.18,2871.82) 912.18,2902 cw(c912.18,2932.18) R37.1@890.84,2910.84 ; R42.2@956.16,2893.16 ccw(c934.82,2871.82) 934.82,2902 ccw(c934.82,2932.18) 956.16,2910.84 ccw(c934.82,2932.18) 965,2932.18 ccw(c995.18,2932.18) R42.2@973.84,2910.84 ; R43.2@956.16,2976.16 cw(c934.82,2954.82) 965,2954.82 cw(c995.18,2954.82) R43.2@973.84,2976.16
HED_LINK_USART_RX: R39.1 U3.26 | length 735.8
  Top Layer w10: 1329.79,2811.54 ccw(c1353.54,2811.54) v1@1336.75,2794.75 ; U3.26@1329.79,2835.68 ccw(c1377.68,2835.68) v1@1343.82,2801.82 ; U3.26@1329.79,2850.61 1329.79,2806.21 v1(1339,2797)
  Bottom Layer w10: v1@1339,2790.19 cw(c1339,2773.75) 1350.63,2785.37 cw(c1362.25,2797) v1@1345.81,2797 ; v1(1339,2797) 1360,2776 1822,2776 1837,2761 R39.1@1873,2761 ; R39.1@1864.16,2752.16 ccw(c1842.82,2730.82) 1842.82,2761 ccw(c1842.82,2791.18) R39.1@1864.16,2769.84
HED_LINK_USART_TX: R40.1 U3.25 | length 779.5
  Top Layer w10: U3.25@1310.1,2850.61 1310.1,2773.9 v1@1321,2763 ; v1@1315.19,2762 ccw(c1298.75,2762) 1310.37,2773.63 ccw(c1322,2785.25) v1@1322,2768.81
  Bottom Layer w10: v1@1322,2755.19 cw(c1322,2738.75) 1333.63,2750.37 cw(c1345.25,2762) v1@1328.81,2762 ; v1(1322,2762) 1336,2748 1797,2748 R40.1@1873,2672 ; R40.1@1860.5,2672 ccw(c1830.32,2672) 1851.66,2693.34 ccw(c1873,2714.68) R40.1@1873,2684.5
LINK_MCU_NRST: P1.5 R38.2 R46.2 R49.2 | length 1017.1
  Top Layer w10: v1(766,2694) 807,2735 R38.2@822,2735 ; v1@766,2700.81 ccw(c766,2717.25) 777.63,2705.63 ccw(c789.25,2694) v1@772.81,2694 ; 775.06,2703.06 cw(c822,2656.11) R38.2@822,2722.5 ; 792.13,2720.13 cw(c822,2690.25) R38.2@822,2732.5
  Bottom Layer w10: P1.5@350,2756 432,2756 460,2728 R49.2@638,2728 732,2728 v1(766,2694) 787,2673 R46.2@822,2673 ; P1.5@358.84,2747.16 cw(c380.18,2725.82) 380.18,2756 cw(c380.18,2786.18) P1.5@358.84,2764.84 ; P1.5@365.91,2740.09 cw(c404.32,2701.68) 404.32,2756 cw(c404.32,2810.32) P1.5@365.91,2771.91 ; R49.2@629.16,2719.16 ccw(c607.82,2697.82) 607.82,2728 ccw(c607.82,2758.18) R49.2@629.16,2736.84 ; R49.2@646.84,2719.16 cw(c668.18,2697.82) 668.18,2728 cw(c668.18,2758.18) R49.2@646.84,2736.84 ; v1@759.19,2694 ccw(c742.75,2694) 754.37,2705.63 ccw(c766,2717.25) v1@766,2700.81 ; v1@766,2687.19 cw(c766,2670.75) 777.63,2682.37 cw(c789.25,2694) v1@772.81,2694 ; R46.2@813.16,2664.16 ccw(c791.82,2642.82) 791.82,2673 ccw(c791.82,2703.18) R46.2@813.16,2681.84
LINK_MCU_SWCLK: P1.4 R41.2 R44.2 R47.2 | length 1104.5
  Top Layer w10: P1.4@350,2856 502,2856 v1(595,2763) R47.2@595,2728 ; P1.4@358.84,2847.16 cw(c380.18,2825.82) 380.18,2856 cw(c380.18,2886.18) P1.4@358.84,2864.84 ; P1.4@365.91,2840.09 cw(c404.32,2801.68) 404.32,2856 cw(c404.32,2910.32) P1.4@365.91,2871.91 ; R47.2@586.16,2736.84 ccw(c564.83,2758.17) v1@595,2758.17 ; v1@588.19,2763 ccw(c571.75,2763) 583.37,2774.63 ccw(c595,2786.25) v1@595,2769.81 ; v1@590.18,2758.18 cw(c578.56,2746.56) 595,2746.56 cw(c611.45,2746.55) v1@599.82,2758.18 ; v1@595,2758.18 ccw(c625.18,2758.18) R47.2@603.84,2736.84 ; v1(788,2819) R41.2@822,2819 ; v1@792.82,2814.18 cw(c804.45,2802.55) 804.45,2819 cw(c804.44,2835.44) v1@792.82,2823.82 ; R41.2@813.16,2810.16 ccw(c791.82,2788.82) 791.82,2819 ccw(c791.82,2849.18) R41.2@813.16,2827.84
  Bottom Layer w10: R44.2@538.16,2838.16 cw(c516.82,2816.82) 547,2816.82 cw(c577.18,2816.82) R44.2@555.84,2838.16 ; R44.2@547,2849 R44.2@547,2847 547,2811 v1(595,2763) 620,2788 733,2788 764,2819 v1(788,2819) ; v1@588.19,2763 ccw(c571.75,2763) 583.37,2774.63 ccw(c595,2786.25) 595,2769.81 ccw(c595,2786.25) 606.63,2774.63 ccw(c618.25,2763) v1@601.81,2763 ; v1@783.18,2814.18 ccw(c771.56,2802.56) 771.56,2819 ccw(c771.56,2835.44) v1@783.18,2823.82
LINK_MCU_SWDIO: P1.3 R37.2 R45.2 R48.2 | length 1134.8
  Top Layer w10: P1.3@350,2956 574,2956 680,2850 R48.2@680,2728 ; P1.3@358.84,2947.16 cw(c380.18,2925.82) 380.18,2956 cw(c380.18,2986.18) P1.3@358.84,2964.84 ; P1.3@365.91,2940.09 cw(c404.32,2901.68) 404.32,2956 cw(c404.32,3010.32) P1.3@365.91,2971.91 ; 667.67,2862.33 cw(c654.33,2849) v1@673.19,2849 ; 670.08,2859.92 ccw(c680,2869.84) v1@680,2855.81 ; R48.2@671.16,2736.84 ccw(c649.83,2758.17) 680,2758.17 ; v1@675.18,2844.18 cw(c663.56,2832.56) 680,2832.56 cw(c696.45,2832.55) v1@684.82,2844.18 ; 680,2758.18 ccw(c710.18,2758.18) R48.2@688.84,2736.84 ; v1(787,2902) R37.2@822,2902 ; v1@791.82,2897.18 cw(c803.44,2885.56) 803.44,2902 cw(c803.45,2918.45) v1@791.82,2906.82 ; R37.2@813.16,2893.16 ccw(c791.82,2871.82) 791.82,2902 ccw(c791.82,2932.18) R37.2@813.16,2910.84
  Bottom Layer w10: R45.2@635,2849 v1(680,2849) 733,2902 v1(787,2902) ; R45.2@643.84,2838.16 cw(c670.01,2811.99) v1@670.01,2849 ; R45.2@643.84,2855.84 ccw(c660.35,2872.35) 660.35,2849 ; v1@675.18,2844.18 ccw(c663.56,2832.56) 663.56,2849 ccw(c663.56,2865.44) v1@675.18,2853.82 ; v1@680,2855.81 ccw(c680,2872.25) 691.63,2860.63 ccw(c703.25,2849) v1@686.81,2849 ; v1@782.18,2897.18 ccw(c770.56,2885.56) 770.56,2902 ccw(c770.56,2918.44) v1@782.18,2906.82
MCU_NRST: R49.1 R54.1 | length 519.6
  Top Layer w10: R54.1@489.16,2437.84 ccw(c467.82,2459.18) 498,2459.18 ccw(c528.18,2459.18) R54.1@506.84,2437.84 ; R54.1@498,2429 498,2466 508,2476 v1(540,2476) ; v1@535.18,2471.18 ccw(c523.56,2459.56) 523.56,2476 ccw(c523.56,2492.44) v1@535.18,2480.82
  Bottom Layer w10: v1(540,2476) 597,2476 667,2546 667,2639 R49.1@638,2668 ; v1@544.82,2471.18 cw(c556.44,2459.56) 556.44,2476 cw(c556.44,2492.44) v1@544.82,2480.82 ; R49.1@638,2655.5 cw(c638,2625.32) 659.34,2646.66 cw(c680.68,2668) R49.1@650.5,2668
MCU_SWCLK: R47.1 R52.1 | length 387.2
  Top Layer w10: R52.1@584,2429 584,2431 654,2501 654,2609 R47.1@595,2668 ; R52.1@584,2441.5 ccw(c584,2466.85) 601.93,2448.93 ; R47.1@595,2655.5 cw(c595,2625.32) 616.34,2646.66 cw(c637.68,2668) R47.1@607.5,2668 ; R52.1@596.5,2429 cw(c631.5,2429) 606.75,2453.75
MCU_SWDIO: R48.1 R53.1 | length 337.9
  Top Layer w10: R53.1@661.16,2437.84 ccw(c639.82,2459.18) 670,2459.18 ccw(c700.18,2459.18) R53.1@678.84,2437.84 ; R53.1@670,2429 670,2461 680,2471 R48.1@680,2668 ; R48.1@671.16,2659.16 cw(c649.82,2637.82) 680,2637.82 cw(c710.18,2637.82) R48.1@688.84,2659.16
NetB2_3: B2.3 B2.4 C8.2 R4.1 R6.2 | length 941.1
  Top Layer w10: B2.3@1600.99,2273.99 v1(1624,2297) ; v1@1617.19,2297 cw(c1600.75,2297) 1612.37,2285.37 cw(c1624,2273.75) v1@1624,2290.19 ; v1@1873,2264.19 cw(c1873,2247.75) 1884.63,2259.37 cw(c1896.25,2271) v1@1879.81,2271 ; v1(1873,2271) 1893.58,2250.42 B2.4@1975.01,2250.42 ; B2.4@1944.79,2232.8 ccw(c1902.24,2190.25) 1902.24,2250.42 ccw(c1902.24,2310.58) B2.4@1944.79,2268.04 ; B2.4@1951.86,2239.87 ccw(c1926.39,2214.39) 1926.39,2250.42 ccw(c1926.39,2286.44) B2.4@1951.86,2260.97
  Bottom Layer w10: v1(1624,2297) 1636,2309 ; v1@1624,2303.81 ccw(c1624,2320.25) 1635.63,2308.63 ccw(c1647.25,2297) v1@1630.81,2297 ; R4.1@1652.24,2301.2 ccw(c1636,2288.22) 1636,2309 ; R4.1@1652.24,2316.81 cw(c1636,2329.79) 1636,2309 ; R4.1@1670.84,2300.16 cw(c1692.18,2278.82) 1692.18,2309 cw(c1692.18,2339.18) R4.1@1670.84,2317.84 ; R6.2@1737.16,2300.16 ccw(c1715.82,2278.82) 1715.82,2309 ccw(c1715.82,2339.18) R6.2@1737.16,2317.84 ; R6.2@1754.84,2300.16 cw(c1776.18,2278.82) 1776.18,2309 cw(c1776.18,2339.18) R6.2@1754.84,2317.84 ; C8.2@1821.16,2300.16 ccw(c1799.82,2278.82) 1799.82,2309 ccw(c1799.82,2339.18) C8.2@1821.16,2317.84 ; C8.2@1830,2296.5 cw(c1830,2251.84) 1861.58,2283.42 ; C8.2@1842.5,2309 ccw(c1858.2,2309) C8.2@1847.1,2297.9 ; 1860.67,2284.33 cw(c1847.33,2271) v1@1866.19,2271 ; 1863.08,2281.92 ccw(c1873,2291.84) v1@1873,2277.81 ; v1@1873,2272 1836,2309 C8.2@1830,2309 R6.2@1746,2309 R4.1@1662,2309 1636,2309
NetBT1_1: BT1.1 R34.2 | length 460.4
  Bottom Layer w20: R34.2@1331.3,525.7 cw(c1344.11,512.89) 1344.11,531 cw(c1344.11,549.11) R34.2@1331.3,536.3 ; 1366.36,531 cw(c1366.36,439.08) BT1.1@1439.51,494.75 ; BT1.1@1406.71,531 cw(c1406.71,469.79) BT1.1@1455.42,506.86 ; BT1.1@1423.59,482.64 ccw(c1326.01,408.37) R34.2@1326,531 1466,531 BT1.1@1493,504
NetC5_2: C5.2 R7.2 Y1.1 | length 426.3
  Top Layer w10: C5.2@760,1139 R7.2@930,1139 ; C5.2@768.84,1130.16 cw(c790.18,1108.82) 790.18,1139 cw(c790.18,1169.18) C5.2@768.84,1147.84 ; C5.2@771.97,1139 ccw(c771.97,1202.49) Y1.1@816.87,1157.6 ; 796.12,1139 ccw(c796.12,1178.35) Y1.1@823.94,1150.53 ; Y1.1@862.06,1150.53 ccw(c889.88,1178.35) 889.88,1139 ; Y1.1@869.13,1157.6 ccw(c914.03,1202.49) 914.03,1139 ; R7.2@927.16,1130.16 ccw(c905.82,1108.82) 905.82,1139 ccw(c905.82,1169.18) R7.2@927.16,1147.84
NetC6_2: C6.2 R8.2 Y1.2 | length 435.6
  Top Layer w10: C6.2@759,1050 C6.2@760,1050 ; C6.2@760,1055 R8.2@930,1055 ; C6.2@768.84,1046.16 cw(c790.18,1024.82) 790.18,1055 cw(c790.18,1085.18) C6.2@768.84,1063.84 ; C6.2@776.8,1055 cw(c776.8,998.33) Y1.2@816.87,1038.4 ; 800.94,1055 cw(c800.94,1022.48) Y1.2@823.94,1045.47 ; 806.8,1055 ccw(c806.8,1069.24) Y1.2@816.87,1059.17 ; Y1.2@862.06,1045.47 cw(c885.06,1022.48) 885.06,1055 ; Y1.2@869.13,1038.4 cw(c909.2,998.33) 909.2,1055 ; Y1.2@869.13,1059.17 ccw(c879.2,1069.24) 879.2,1055 ; R8.2@924.79,1048.79 R8.2@930,1054 ; R8.2@927.16,1046.16 ccw(c905.82,1024.82) 905.82,1055 ccw(c905.82,1085.18) R8.2@927.16,1063.84
NetC8_1: C8.1 R5.1 | length 178.8
  Bottom Layer w10: C8.1@1830,2369 R5.1@1914,2369 ; C8.1@1838.84,2360.16 cw(c1860.18,2338.82) 1860.18,2369 cw(c1860.18,2399.18) C8.1@1838.84,2377.84 ; R5.1@1905.16,2360.16 ccw(c1883.82,2338.82) 1883.82,2369 ccw(c1883.82,2399.18) R5.1@1905.16,2377.84
NetC11_1: C11.1 R9.1 Y2.1 | length 574.6
  Top Layer w10: Y2.1@750.82,894.99 ccw(c722.39,923.42) 762.6,923.42 ccw(c802.8,923.42) Y2.1@774.37,894.99 ; Y2.1@762.6,879.28 762.6,942.6 C11.1@769,949 769,963 794,988 ; Y2.1@762.6,903.36 cw(c814.63,903.36) C11.1@777.84,940.16 ; 762.6,927.51 cw(c790.49,927.51) C11.1@770.77,947.23 ; C11.1@771.48,949.33 cw(c800.22,953.2) 779.71,973.71 ; C11.1@781.39,950.67 cw(c825.4,956.6) 794,988 ; R9.1@923.5,877 ccw(c893.32,877) 914.66,898.34 ccw(c936,919.68) R9.1@936,889.5 ; R9.1@936,877 892,921 892,962 866,988 794,988
NetC12_1: C12.1 R10.1 Y2.3 | length 376.7
  Top Layer w10: C12.1@820.16,724.84 ccw(c798.82,746.18) 829,746.18 ccw(c859.18,746.18) C12.1@837.84,724.84 ; C12.1@829,729.36 cw(c886.18,729.36) Y2.3@848.4,772.29 ; C12.1@829,730 Y2.3@829,782.6 ; 829,751.49 cw(c866.71,751.49) Y2.3@841.8,779.79 ; Y2.3@837.4,788.72 919.72,788.72 R10.1@922,791 ; Y2.3@849.18,776.95 cw(c877.61,748.52) 877.61,788.72 cw(c877.61,828.93) Y2.3@849.18,800.5 ; 900.33,788.72 ccw(c900.33,826.67) R10.1@927.16,799.84 ; 911.31,788.72 cw(c911.31,766.31) R10.1@927.16,782.16
NetC22_2: C22.2 C28.2 U3.32 | length 369.8
  Top Layer w10: U3.32@1447.9,2850.61 1459.39,2850.61 1543.5,2766.5 1547,2763 C28.2@1633,2763 ; U3.32@1448.26,2848.28 cw(c1453.89,2842.65) 1453.89,2850.61 ; 1522.42,2787.58 ccw(c1554,2819.16) C22.2@1554,2774.5 ; C22.2@1536.9,2773.1 cw(c1525.81,2762) C22.2@1541.5,2762 ; C22.2@1562.84,2753.16 cw(c1586.59,2729.41) 1586.59,2763 ; C22.2@1562.84,2770.84 ccw(c1581.76,2789.76) 1581.76,2763 ; 1605.41,2763 cw(c1605.41,2729.41) C28.2@1629.16,2753.16 ; 1610.24,2763 ccw(c1610.24,2789.76) C28.2@1629.16,2770.84
NetC24_2: C24.2 R1.1 R2.1 U1.5 | length 579.1
  Top Layer w10: U1.5@1218.57,1060.12 1257.12,1060.12 1283,1086 v1(1283,1105) ; U1.5@1248.09,1060.04 ccw(c1248.09,1081.63) 1263.36,1066.36 ; v1@1278.18,1100.18 cw(c1266.56,1088.56) 1283,1088.56 cw(c1299.44,1088.56) v1@1287.82,1100.18
  Bottom Layer w10: v1@1278.18,1109.82 ccw(c1266.56,1121.44) 1283,1121.44 ccw(c1299.44,1121.44) v1@1287.82,1109.82 ; v1(1283,1105) 1283,1166 1324,1207 C24.2@1324,1212 ; 1299.12,1182.12 ccw(c1269.25,1212) C24.2@1311.5,1212 ; 1311.2,1194.2 cw(c1324,1181.39) C24.2@1324,1199.5
  Bottom Layer w20: R2.1@1243,1295 R1.1@1341,1295 1341,1250 1324,1233 C24.2@1324,1212 ; R2.1@1248.3,1289.7 cw(c1261.11,1276.89) 1261.11,1295 cw(c1261.11,1313.11) R2.1@1248.3,1300.3 ; R1.1@1335.7,1289.7 ccw(c1322.89,1276.89) 1322.89,1295 ccw(c1322.89,1313.11) R1.1@1335.7,1300.3
NetC27_2: C27.2 R36.2 U5.2 | length 601.5
  Bottom Layer w10: U5.2@1619,1900 U5.2@1619,1932.95 U5.2@1619,1940
  Bottom Layer w20: U5.2@1610.76,1961.86 ccw(c1590.87,1981.76) 1619,1981.76 ccw(c1647.13,1981.76) U5.2@1627.24,1961.86 ; U5.2@1619,1900 1707,1812 R36.2@1707,1799 ; U5.2@1619,1940 1619,2000 1646,2027 C27.2@1815,2027 ; U5.2@1630.65,1912.28 ccw(c1688.44,1912.28) 1647.58,1871.42 ; 1685,1834 cw(c1650,1799) R36.2@1699.5,1799 ; C27.2@1809.7,2021.7 ccw(c1796.89,2008.89) 1796.89,2027 ccw(c1796.89,2045.11) C27.2@1809.7,2032.3
NetCN1_25: CN1.25 R16.1 | length 1335.6
  Top Layer w10: v1@395,960.42 574.42,960.42 v1(591,977) ; v1@399.82,955.18 cw(c412.45,942.55) 412.45,960.42 ; v1@399.82,964.82 ccw(c410.44,975.44) 410.44,960.42 ; v1@584.19,977 cw(c567.75,977) 579.37,965.37 cw(c591,953.75) v1@591,970.19
  Bottom Layer w10: CN1.25@148,793.23 197.42,842.65 ; CN1.25@149.28,814.61 ccw(c151.79,856.81) 181.69,826.91 ccw(c211.58,797.02) CN1.25@169.38,794.5 ; CN1.25@149.87,824.59 ccw(c153.57,886.49) 197.41,842.64 ; CN1.25@179.36,795.1 cw(c241.27,798.79) 197.42,842.64 ; v1@390.18,955.18 ccw(c378.56,943.56) 378.56,960 ccw(c378.56,976.44) v1@390.18,964.82 ; v1(395,960) 297,960 281,944 212,944 197.42,929.42 197.42,842.65 ; v1(591,977) 610,996 610,1091 791,1272 R16.1@841,1272 ; v1@591,983.81 ccw(c591,1000.25) 602.63,988.63 ccw(c614.25,977) v1@597.81,977 ; R16.1@832.16,1263.16 ccw(c810.82,1241.82) 810.82,1272 ccw(c810.82,1302.18) R16.1@832.16,1280.84 ; R16.1@841,1268 R16.1@852,1268
NetCN1_27: CN1.27 R17.1 | length 1309.7
  Top Layer w10: v1(537,861) v1(603,927) ; v1@537,867.81 ccw(c537,884.25) 548.63,872.63 ccw(c560.25,861) v1@543.81,861 ; v1@596.19,927 cw(c579.75,927) 591.37,915.37 cw(c603,903.75) v1@603,920.19
  Bottom Layer w10: CN1.27@148,693.23 197.77,743 ; CN1.27@149.16,714.61 ccw(c151.5,757.59) 181.93,727.16 ccw(c212.36,696.72) CN1.27@169.39,694.39 ; CN1.27@149.7,724.6 ccw(c153.13,787.64) 197.77,743 ; CN1.27@179.37,694.93 cw(c242.41,698.36) 197.77,743 ; v1@530.19,861 cw(c513.75,861) 525.37,849.37 cw(c537,837.75) v1@537,854.19 ; v1(537,861) 487,811 377,811 309,743 197.77,743 ; v1(603,927) 636,960 636,1081 745,1190 R17.1@841,1190 ; v1@603,933.81 ccw(c603,950.25) 614.63,938.63 ccw(c626.25,927) v1@609.81,927 ; R17.1@832.16,1181.16 ccw(c810.82,1159.82) 810.82,1190 ccw(c810.82,1220.18) R17.1@832.16,1198.84 ; R17.1@841,1186 R17.1@852,1186
NetCN1_29: CN1.29 R18.1 | length 1844.4
  Bottom Layer w10: CN1.29@148,593.23 198.77,644 ; CN1.29@148.85,614.63 ccw(c150.63,659.81) 182.61,627.84 ccw(c214.58,595.86) CN1.29@169.4,594.07 ; CN1.29@149.24,624.62 ccw(c151.86,690.9) 198.77,644 ; CN1.29@179.39,594.47 cw(c245.67,597.09) 198.77,644 ; 359,545 359,571 ; 359,583 359,571 ; 842,154 836,154 ; R18.1@983.16,462.16 cw(c961.82,440.82) 992,440.82 cw(c1022.18,440.82) R18.1@1000.84,462.16 ; R18.1@992,471 992,248 898,154 836,154 ; 198.77,644 313,644 359,598 359,571 ; 359,571 359,190 395,154 836,154
NetCN1_31: CN1.31 R19.1 | length 1802.3
  Bottom Layer w10: CN1.31@148,493.23 198.77,544 ; CN1.31@148.85,514.63 ccw(c150.63,559.81) 182.61,527.84 ccw(c214.58,495.86) CN1.31@169.4,494.07 ; CN1.31@149.24,524.62 ccw(c151.86,590.9) 198.77,544 ; CN1.31@179.39,494.47 cw(c245.67,497.09) 198.77,544 ; R19.1@1067.16,462.16 cw(c1045.82,440.82) 1076,440.82 cw(c1106.18,440.82) R19.1@1084.84,462.16 ; R19.1@1076,471 1076,275 932,131 378,131 321,188 321,521 298,544 228,544 198.77,544
NetCN1_36: CN1.36 CN3.5 R20.1 R23.2 | length 1392.7
  Top Layer w10: CN1.36@248,293.23 325.23,293.23 343,311 CN3.5@429,311 CN3.5@416,298 ; CN1.36@263.14,278.08 cw(c299.71,241.52) 299.71,293.23 cw(c299.71,344.93) CN1.36@263.14,308.37 ; CN1.36@270.22,271.01 cw(c323.85,217.38) 323.85,293.23 cw(c323.85,369.08) CN1.36@270.22,315.44 ; CN3.5@406.78,288.78 ccw(c353.15,235.15) 353.15,311 ccw(c353.15,386.85) CN3.5@406.78,333.22 ; CN3.5@413.86,295.86 ccw(c377.29,259.29) 377.29,311 ccw(c377.29,362.71) CN3.5@413.86,326.14
  Bottom Layer w10: CN3.5@429,311 654,311 R20.1@745,402 ; CN3.5@444.14,295.86 cw(c480.71,259.29) 480.71,311 cw(c480.71,362.71) CN3.5@444.14,326.14 ; CN3.5@451.22,288.78 cw(c504.85,235.15) 504.85,311 cw(c504.85,386.85) CN3.5@451.22,333.22 ; 720.54,377.54 cw(c747,351.08) R20.1@747,388.5 ; 727.78,384.78 ccw(c711.56,401) R20.1@734.5,401 ; R20.1@738.16,409.84 ccw(c716.82,431.18) 747,431.18 ccw(c777.18,431.18) R20.1@755.84,409.84 ; R23.2@738.16,481.16 cw(c716.82,459.82) 747,459.82 cw(c777.18,459.82) R23.2@755.84,481.16 ; R20.1@747,401 R23.2@747,490
NetCN1_38: CN1.38 CN3.6 R21.1 R22.2 | length 1345.8
  Top Layer w10: CN1.38@248,193.23 325.23,193.23 343,211 CN3.6@429,211 ; CN1.38@263.14,178.08 cw(c299.71,141.52) 299.71,193.23 cw(c299.71,244.93) CN1.38@263.14,208.37 ; CN1.38@270.22,171.01 cw(c323.85,117.38) 323.85,193.23 cw(c323.85,269.08) CN1.38@270.22,215.44 ; CN3.6@406.78,188.78 ccw(c353.15,135.15) 353.15,211 ccw(c353.15,286.85) CN3.6@406.78,233.22 ; CN3.6@413.86,195.86 ccw(c377.29,159.29) 377.29,211 ccw(c377.29,262.71) CN3.6@413.86,226.14 ; CN3.6@423,198 CN3.6@429,204
  Bottom Layer w10: CN3.6@429,211 741,211 R21.1@745,215 ; CN3.6@444.14,195.86 cw(c480.71,159.29) 480.71,211 cw(c480.71,262.71) CN3.6@444.14,226.14 ; CN3.6@451.22,188.78 cw(c504.85,135.15) 504.85,211 cw(c504.85,286.85) CN3.6@451.22,233.22 ; 707.16,211 ccw(c707.16,254.84) 738.16,223.84 ccw(c716.82,245.18) 747,245.18 ccw(c777.18,245.18) R21.1@755.84,223.84 ; 726.48,211 cw(c726.48,194.48) R21.1@738.16,206.16 ; R22.2@738.16,294.16 cw(c716.82,272.82) 747,272.82 cw(c777.18,272.82) R22.2@755.84,294.16 ; R21.1@747,215 R22.2@747,303
NetCN2_1: CN2.1 R24.2 | length 393.7
  Bottom Layer w10: CN2.1@428,1599 CN2.1@433,1604 ; CN2.1@429,1611 558,1611 R24.2@565,1604 ; CN2.1@444.14,1595.86 cw(c480.71,1559.29) 480.71,1611 cw(c480.71,1662.71) CN2.1@444.14,1626.14 ; CN2.1@451.22,1588.78 cw(c504.85,1535.15) 504.85,1611 cw(c504.85,1686.85) CN2.1@451.22,1633.22 ; 534.82,1611 cw(c534.82,1580.82) R24.2@556.16,1602.16 ; 534.83,1611 ccw(c534.83,1641.17) R24.2@556.16,1619.84
NetCN4_8: CN4.8 CN6.7 R26.2 | length 1102
  Bottom Layer w10: R26.2@2219.7,1783.7 ccw(c2250.35,1814.35) 2250.35,1771 ; R26.2@2225,1789 2243,1771 CN4.8@2329,1771 ; R26.2@2226.77,1790.77 ccw(c2274.49,1838.49) 2274.49,1771 ; R26.2@2233.84,1797.84 ccw(c2298.64,1862.64) CN4.8@2298.64,1771 ; CN4.8@2306.78,1748.78 ccw(c2253.15,1695.15) 2253.15,1771 ccw(c2253.15,1846.85) CN4.8@2306.78,1793.22 ; CN4.8@2313.86,1755.86 ccw(c2277.29,1719.29) 2277.29,1771 ccw(c2277.29,1822.71) CN4.8@2313.86,1786.14 ; CN4.8@2329,1769 2452.23,1769 CN6.7@2528,1693.23 ; CN4.8@2344.14,1755.86 cw(c2375.88,1724.12) 2375.88,1769 ; CN4.8@2344.14,1786.14 ccw(c2385.53,1827.53) 2385.53,1769 ; CN4.8@2351.22,1748.78 cw(c2400.02,1699.98) 2400.02,1769 ; CN4.8@2351.22,1793.22 ccw(c2409.68,1851.68) 2409.68,1769 ; CN6.7@2496.58,1693.23 ccw(c2420.73,1693.23) 2474.37,1746.86 ccw(c2528,1800.49) CN6.7@2528,1724.65 ; CN6.7@2506.58,1693.23 ccw(c2454.88,1693.23) 2491.44,1729.79 ccw(c2528,1766.35) CN6.7@2528,1714.65
NetCN6_36: CN6.36 R27.2 | length 648.3
  Bottom Layer w10: R27.2@2224,362 2381,362 2397.19,345.81 2559.19,345.81 2611.77,293.23 CN6.36@2628,293.23 ; R27.2@2234.84,353.16 cw(c2256.18,331.83) 2256.18,362 cw(c2256.18,392.18) R27.2@2234.84,370.84 ; 2567.31,337.69 ccw(c2605.83,376.22) CN6.36@2619.89,323.58 ; 2579.56,325.44 ccw(c2611,356.87) CN6.36@2622.47,313.92 ; 2585.84,319.16 cw(c2559.91,293.23) CN6.36@2596.58,293.23 ; 2591.82,313.18 ccw(c2616.17,337.52) CN6.36@2625.05,304.26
